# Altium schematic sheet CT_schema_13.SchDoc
size 147 x 119 mm
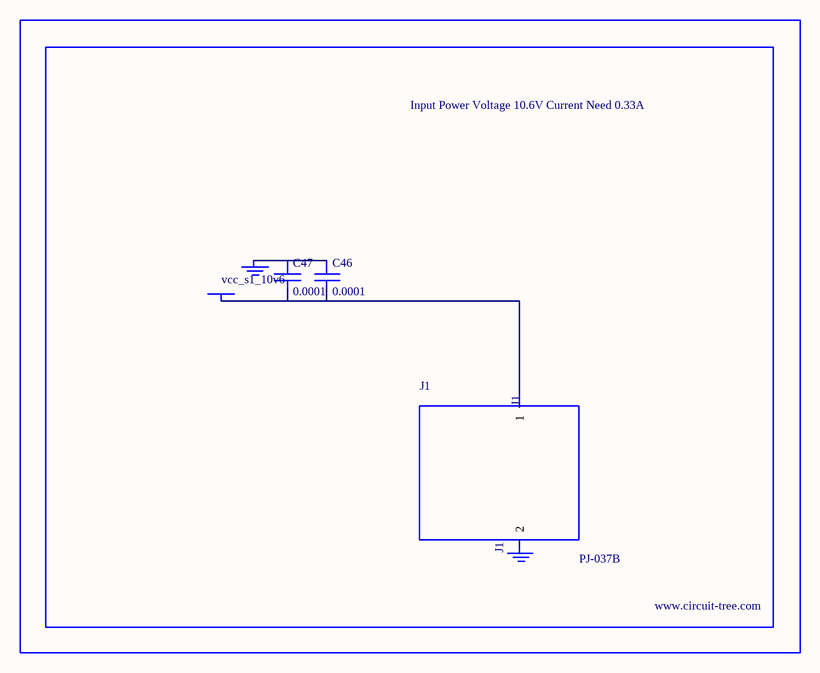
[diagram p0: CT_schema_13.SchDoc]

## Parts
BORDER12  (no value)
C46  0.0001  [EXV-9H]
C47  0.0001  [EXV-9H]
GND_INSTANCE_12_0  (no value)
GND_INSTANCE_12_1  (no value)
J1  PJ-037B  [PJ-037B_PACKAGE]
POWER_INSTANCE_12_0  vcc_s1_10v6

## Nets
NetC46_1: C46.1 C47.1 GND_INSTANCE_12_0.0(GND)
NetC46_2: C46.2 C47.2 J1.1 POWER_INSTANCE_12_0.0(PWR)

Not connected (* = marked no-connect by the designer): GND_INSTANCE_12_1 0(GND); J1 2

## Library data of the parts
BORDER12 = BORDER_PAGE12
C46 C47 = EDK107M035A9HAA
GND_INSTANCE_12_0 GND_INSTANCE_12_1 = GND
POWER_INSTANCE_12_0 = PWR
